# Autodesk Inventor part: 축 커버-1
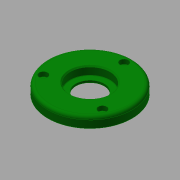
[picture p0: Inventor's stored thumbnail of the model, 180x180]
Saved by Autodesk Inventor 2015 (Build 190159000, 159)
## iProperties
Created: 2015-10
Part Number: 축 커버-1
Document SubType Name: Modeling
Designer: mdu
Density: 7.86 g/cm^3
Material: 강철, 연강
Appearance: 진녹색
Mass: 324.903 g
Surface Area: 132.124 cm^2
Volume: 41.3362 cm^3
Author: mdu
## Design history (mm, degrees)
sketch "스케치1"
  geometry: C1 r 40 at (0, 0) reference; C2 r 26 at (0, 0) reference; 1 further point
  node "참조1"
  node "참조2"
extrude "돌출1" new body sketch "스케치1" distance "d0" = 10; taper "d1" = 0 deg
extrude "돌출2" join sketch "스케치1" distance "d2" = 3; taper "d3" = 0 deg
hole "구멍1" diameter "d6" = 27; stored, may be unused: countersink angle "d10" = 90 deg, drill point angle "d12" = 118 deg; dims "d4" = 10, "d5" = 10, "d7" = 6, "d8" = 38, "d9" = 8, "d11" = 8
sketch "스케치2"
  geometry: C1 r 20 at (0, 0); 1 further point
  constraints: 1 centre point, 1 coincident
  dimensions: "d13" = 40 diameter of C1
extrude "돌출3" cut sketch "스케치2" distance "d14" = 3; taper "d15" = 0 deg
sketch "스케치3"
  geometry: C1 r 1.621 at (0, 32.5) reference; 1 further point
hole "구멍2" sketch "스케치3" at (0, 32.5) diameter "d16" = 4.5; stored, may be unused: countersink angle "d20" = 90 deg, drill point angle "d22" = 118 deg; dims "d17" = 6, "d18" = 8, "d19" = 4.4, "d21" = 8
fillet "모깎기1" dims "d26" = 3, "d27" = 0.3
chamfer "모따기1" distance "d28" = 1; stored, may be unused: second distance "d29" = 2, angle "d30" = 45 deg
node "솔리드1"
pattern_circular "원형 패턴1" dims angle "d24" = 360 deg
node "참조3"
